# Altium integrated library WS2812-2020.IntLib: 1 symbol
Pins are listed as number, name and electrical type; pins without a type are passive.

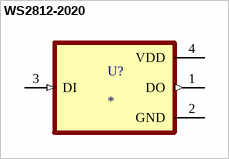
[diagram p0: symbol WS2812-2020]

## WS2812-2020
designator U?
Intelligent control LED light source, SMD-4; MP: WS2812-2020; MF: Worldsemi
footprint LED_WS2812-2020
pins: 1 DO (out), 2 GND (power), 3 DI (in), 4 VDD (power)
